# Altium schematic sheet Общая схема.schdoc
size 247 x 167 mm
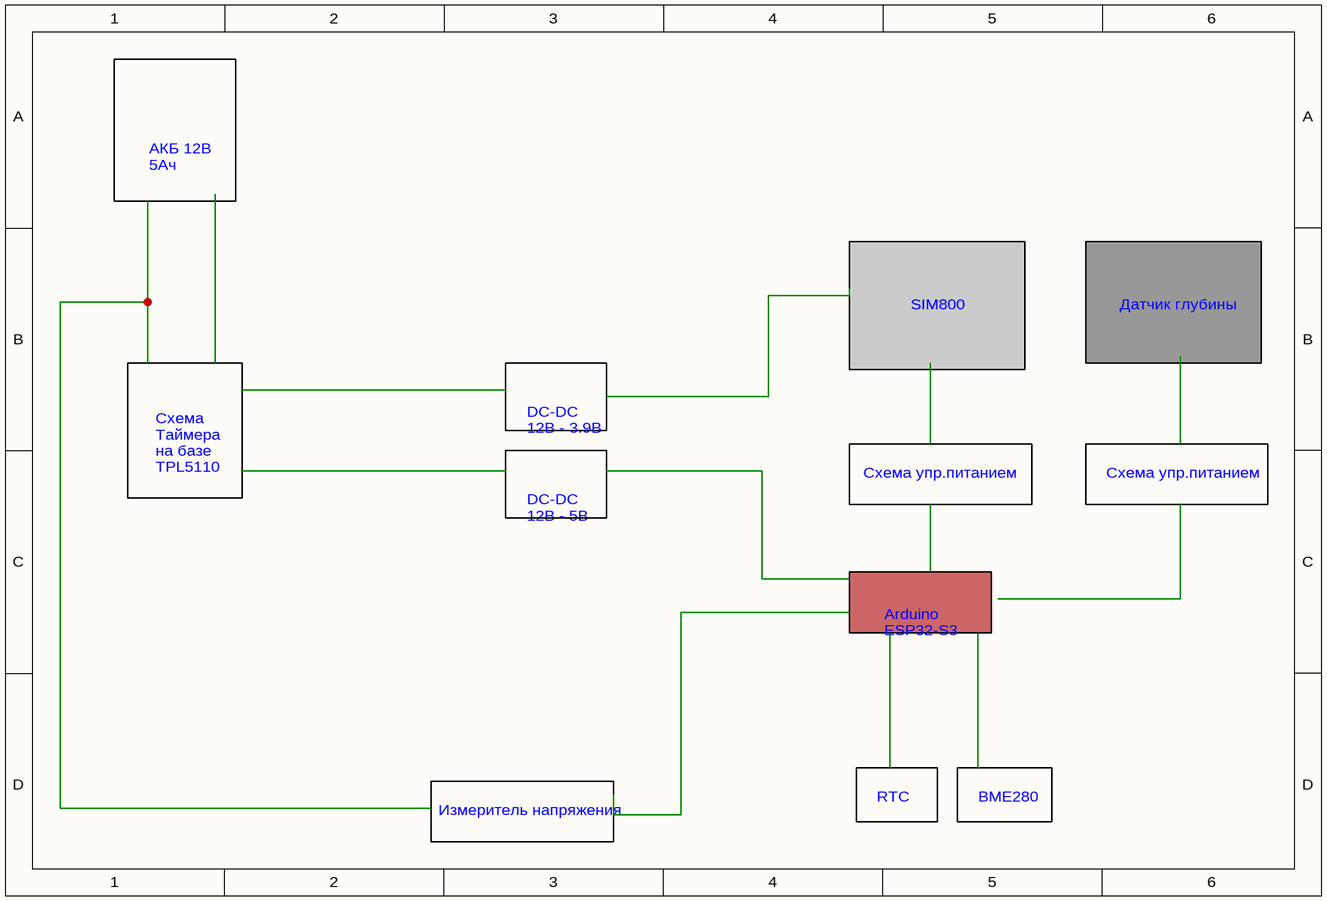
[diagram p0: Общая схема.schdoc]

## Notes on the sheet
- АКБ 12В
  5Ач
- SIM800
- Датчик глубины
- Схема
  Таймера
  на базе
  TPL5110
- DC-DC
  12В - 3.9В
- DC-DC
  12В - 5В
- Схема упр.питанием
- Arduino
  ESP32-S3
- Измеритель напряжения
- RTC
- BME280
